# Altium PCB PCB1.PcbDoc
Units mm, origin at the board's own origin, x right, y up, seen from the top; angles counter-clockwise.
Board outline 108.58 x 46.35 mm, 3 copper layers (Top Layer, Mid-Layer 1, Bottom Layer); 29 components, 33 nets, 133 pads, 11 vias.
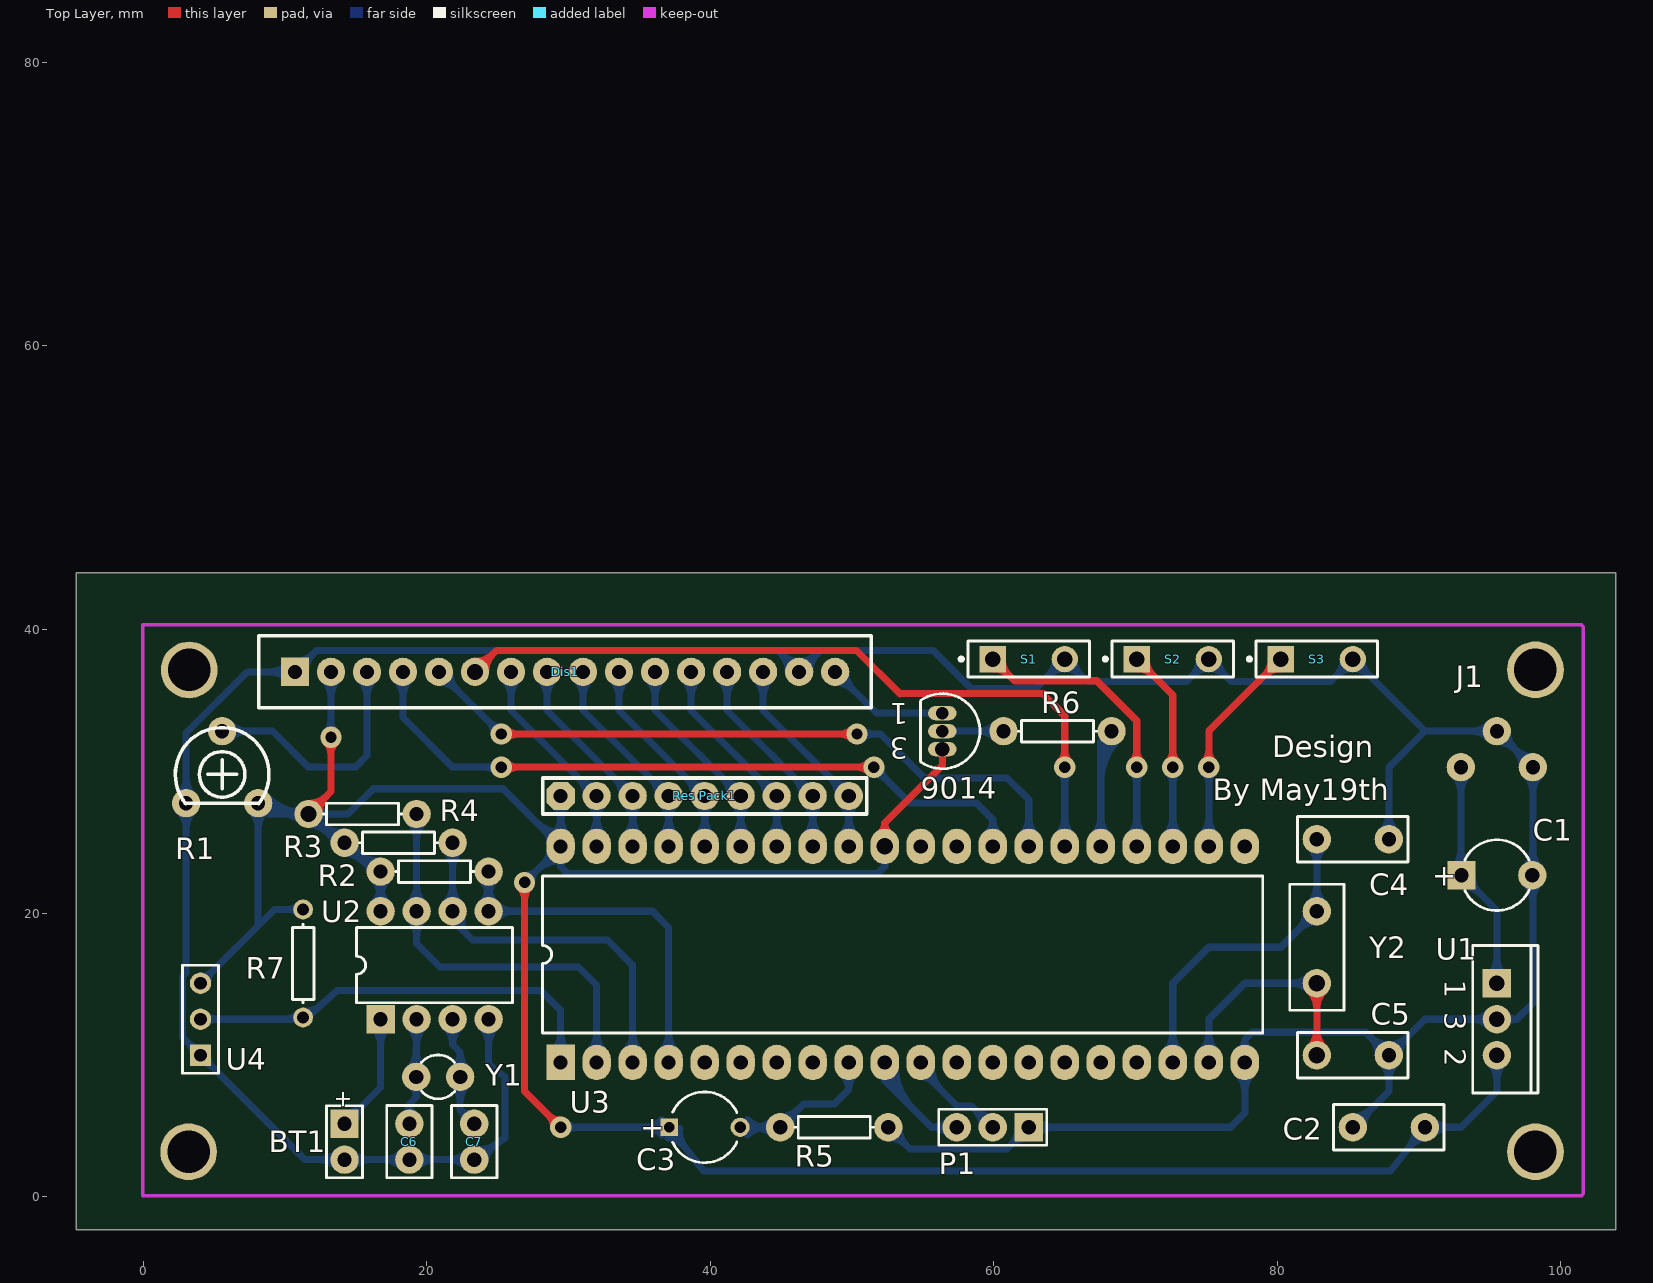
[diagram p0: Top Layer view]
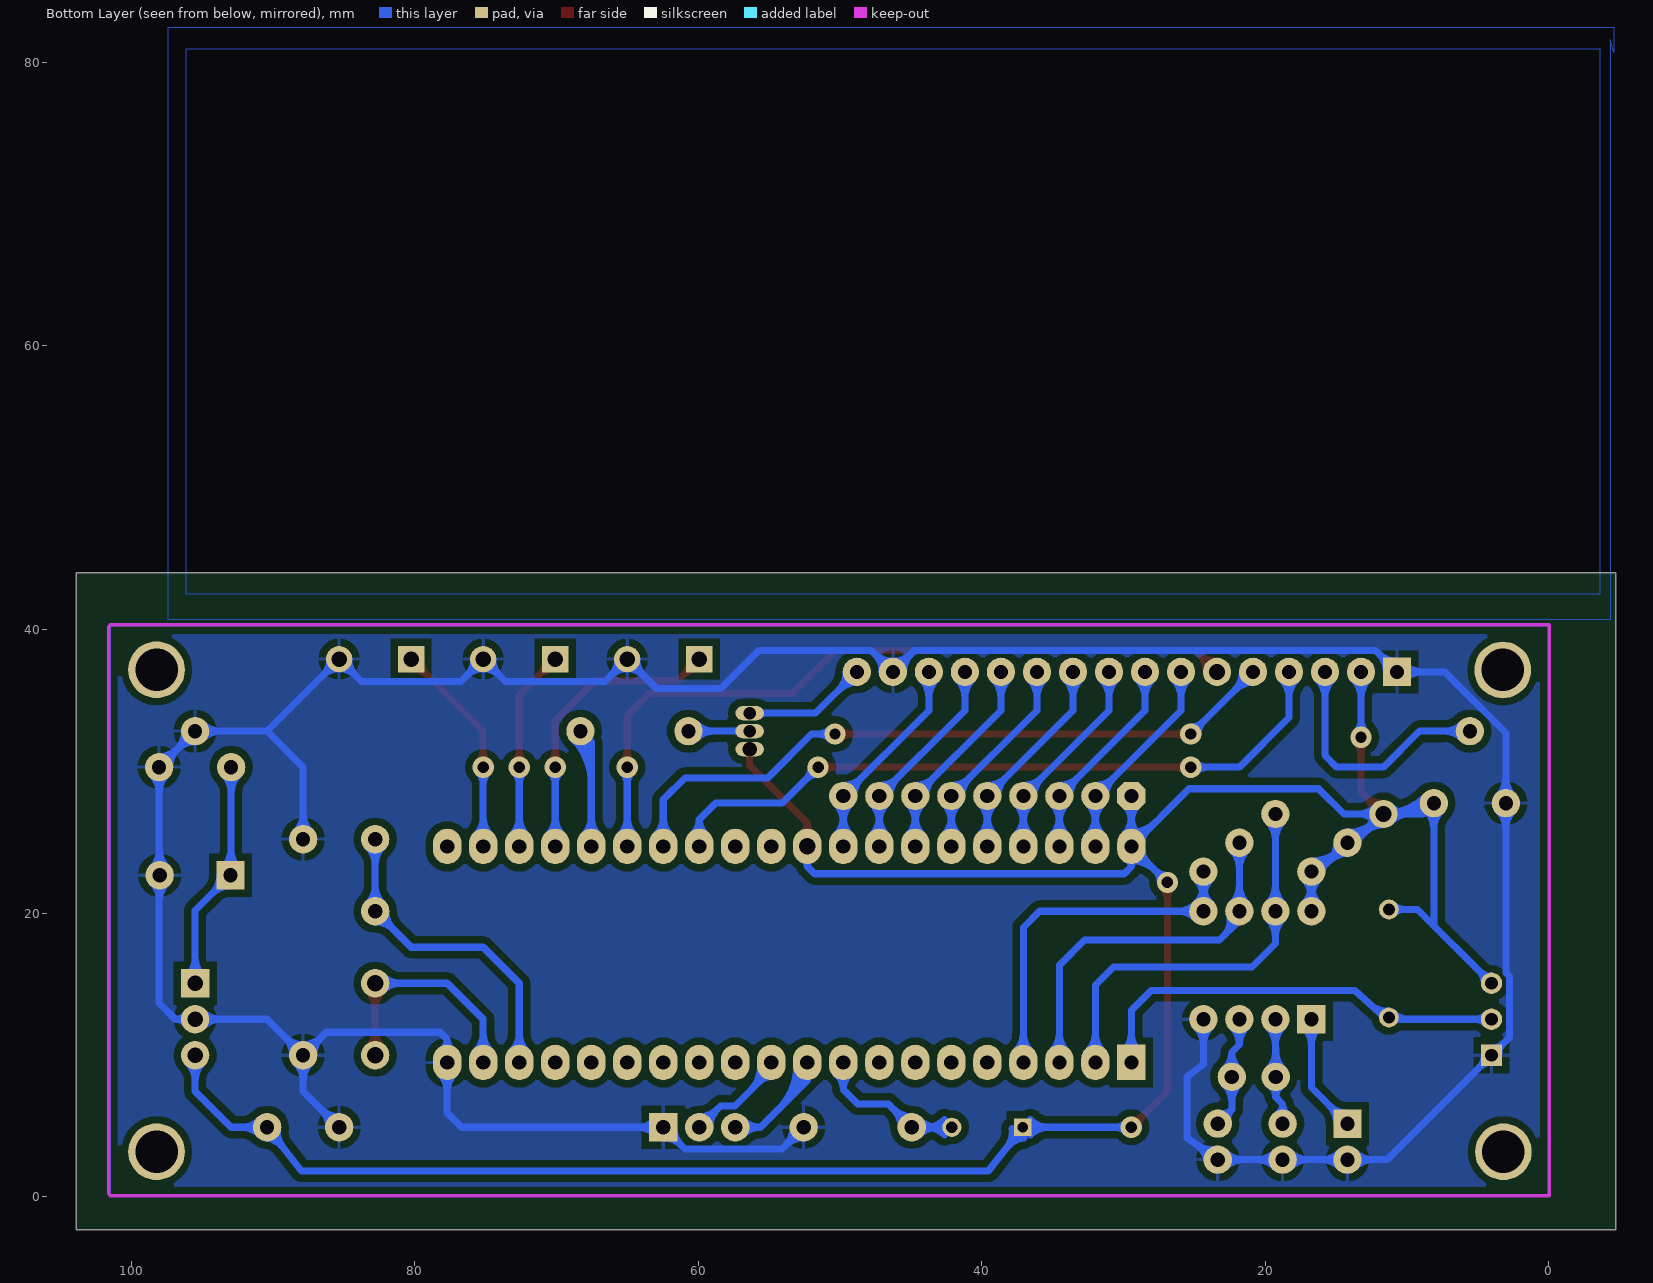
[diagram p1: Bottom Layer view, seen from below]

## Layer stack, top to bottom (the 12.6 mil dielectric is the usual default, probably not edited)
Top Layer: signal copper 0.0356
Dielectric: dielectric 0.32, FR-4, Dk 4.8
Mid-Layer 1: signal copper 0.0356
Dielectric: dielectric 0.32, FR-4, Dk 4.8
Bottom Layer: signal copper 0.0356

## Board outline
-4.715,43.623 -4.715,-2.351 103.87,-2.351 103.87,44.004 -4.715,44.004

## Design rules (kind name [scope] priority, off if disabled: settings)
Clearance [All] p1: gap=0.254
ComponentClearance [All] p1: gap=0.254 collisioncheckmode=0
PolygonConnect [All] p1: connectstyle=Relief reliefconductorwidth=0.254 reliefentries=4 polygonreliefangle="90 Angle"
RoutingVias [All] p1: holewidth=0.711 width=1.27 viastyle="Through Hole" minholewidth=0.711 minwidth=1.27 maxholewidth=0.711 maxwidth=1.27
SolderMaskExpansion [All] p1: expansion=0.203
TestPointUsage [All] p1: valid=0 allowmultiple=FALSE
Testpoint [All] p1: side=15 testpointundercomponent=TRUE minsize=1.016 maxsize=2.54 preferedsize=1.524 minholesize=0 maxholesize=1.016 preferedholesize=0.813 testpointgrid=0.025 style=1023 order=-539222988
Width [All] p1: maxlimit=0.5 minlimit=0.254 preferedwidth=0.254 toplayer_minwidth=0.5 toplayer_prefwidth=0.5 midlayer1_maxwidth=0.254 bottomlayer_minwidth=0.5 bottomlayer_prefwidth=0.5 minimp=50.000000 maximp=50.000000 favimp=50.000000
17 further rules are at their usual default settings.

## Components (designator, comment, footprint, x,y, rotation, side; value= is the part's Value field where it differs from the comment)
9014 "NPN" BCY-W3 56.372,32.828 r180 top (schematic designator Q1)
BT1 "Battery" BAT-2 14.208,3.872 r270 top
C1 "Cap Pol1" CAPPR5-5x5#1 95.488,22.668 r0 top
C2 "Cap" CAPR5.08-7.8x3.2#1 87.868,4.888 r0 top
C3 "Cap Pol1" CAPPR5-5x5#2 39.608,4.888 r0 top
C4 "Cap" CAPR5.08-7.8x3.2#1 85.328,25.208 r180 top
C5 "Cap" CAPR5.08-7.8x3.2#2 85.328,9.968 r180 top
C6 "Cap" CAPR2.54-5.1x3.2 18.78,3.872 r90 top
C7 "Cap" CAPR2.54-5.1x3.2 23.352,3.872 r90 top
Dis1 "LCD1602 BIG" 1602 10.708,37.008 r0 top locked
J1 "电源插头" "电源插头 小" 92.948,30.288 r90 top
P1 "Header 3" HDR1X3#1 62.468,4.888 r180 top
R1 "RPot" 蓝白可调 5.572,32.828 r0 top
R2 "Res1" AXIAL-0.3#1 20.558,22.922 r180 top
R3 "Res1" AXIAL-0.3#1 18.018,24.954 r180 top
R4 "Res1" AXIAL-0.3#2 15.478,26.986 r180 top
R5 "Res1" AXIAL-0.3#1 48.752,4.888 r180 top
R6 "Res1" AXIAL-0.3#1 64.5,32.828 r180 top
R7 "Res1" AXIAL-0.3#3 11.287,16.445 r270 top
"Res Pack1" "RES Pack" "Res Pack" 29.448,28.256 r90 top locked
S1 "SW-PB" SPST-2 62.468,37.908 r0 top
S2 "SW-PB" SPST-2 72.628,37.908 r0 top
S3 "SW-PB" SPST-2 82.788,37.908 r0 top
U1 "L7805AB-V" TO220ABN 95.488,12.508 r270 top
U2 "DS1302" DIP8 20.558,16.318 r0 top
U3 "STC89C51" DIP40 29.448,9.46 r90 top
U4 "DS18b20" HDR1X3#2 4.048,9.968 r90 top
Y1 "XTAL" BCY-W2/D3.1 20.812,8.444 r270 top
Y2 "XTAL" RAD-0.2 82.788,17.588 r270 top

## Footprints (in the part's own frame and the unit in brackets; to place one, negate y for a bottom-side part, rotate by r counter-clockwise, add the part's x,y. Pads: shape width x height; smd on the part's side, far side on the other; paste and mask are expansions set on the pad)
1602 [mm]
  rect 2x2 hole 1: 1(0,0)
  round 2 hole 1: 2(2.54,0) 3(5.08,0) 4(7.62,0) 5(10.16,0) 7(15.24,0) 8(17.78,0) 9(20.32,0) 10(22.86,0) 11(25.4,0) 12(27.94,0) 13(30.48,0) 14(33.02,0) 15(35.56,0) 16(38.1,0)
  round 2 hole 1.15: 6(12.7,0)
  silkscreen extent -2.54,-2.54 40.64,2.54
AXIAL-0.3#1 [mm] "Resistor; 2 Leads"
  round 2 hole 1: 1(-3.81,0) 2(3.81,0)
  silkscreen extent -2.77,-0.76 2.77,0.76
AXIAL-0.3#2 [mm] "Resistor; 2 Leads"
  round 2 hole 1: 1(-3.81,0)
  round 2 hole 1.15: 2(3.81,0)
  silkscreen extent -2.77,-0.76 2.77,0.76
AXIAL-0.3#3 [mm] "Resistor; 2 Leads"
  round 1.4 hole 0.85: 1(-3.81,0) 2(3.81,0)
  silkscreen extent -2.77,-0.76 2.77,0.76
BAT-2 [mm] "Multicell Battery; 2 Leads"
  rect 2x2 hole 1: 1(-1.27,0)
  round 2 hole 1: 2(1.27,0)
  silkscreen extent -2.54,-1.27 2.54,1.27
BCY-W2/D3.1 [mm] "Crystal, Thru-Hole; 2 Leads; Body 3.1 x 8.2 mm (Dia.xH)"
  round 2 hole 1: 1(0,1.55) 2(0,-1.55)
  silkscreen extent -1.55,-1.19 1.55,1.17
BCY-W3 [mm] "TO, Flat Index; 3 In-Line, Axial Leads; Body Dia. 4.8mm"
  oval 2x1 hole 0.9: 1(0,-1.27) 2(0,0)
  oval 2x1 hole 1: 3(0,1.27)
  silkscreen extent -2.65,-2.65 1.55,2.65
CAPPR5-5x5#1 [mm] "Capacitor, Electrolytic, Radial; Body 5 x 5 mm (Dia.xH typ); Pin Spacing 5 mm (typ)"
  rect 2x2 hole 1: 1(-2.5,0)
  round 2 hole 1: 2(2.5,0)
  silkscreen extent -2.26,-2.5 2.27,2.5
CAPPR5-5x5#2 [mm] "Capacitor, Electrolytic, Radial; Body 5 x 5 mm (Dia.xH typ); Pin Spacing 5 mm (typ)"
  rect 1.25x1.25 hole 0.75: 1(-2.5,0)
  round 1.35 hole 0.8: 2(2.5,0)
  silkscreen extent -2.26,-2.5 2.27,2.5
CAPR2.54-5.1x3.2 [mm] "Capacitor, Ceramic, Thru-Hole, Dipped Radial; Body 5.1 x 3.2 mm (WxT) Pin Spacing 2.54 mm (typ)"
  round 2 hole 1: 1(-1.27,0) 2(1.27,0)
  silkscreen extent -2.55,-1.6 2.55,1.6
CAPR5.08-7.8x3.2#1 [mm] "Capacitor, Ceramic, Thru-Hole, Dipped Radial; Body 7.8 x 3.2 mm (WxT) Pin Spacing 5.08 mm (typ)"
  round 2 hole 1: 1(-2.54,0) 2(2.54,0)
  silkscreen extent -3.9,-1.6 3.9,1.6
CAPR5.08-7.8x3.2#2 [mm] "Capacitor, Ceramic, Thru-Hole, Dipped Radial; Body 7.8 x 3.2 mm (WxT) Pin Spacing 5.08 mm (typ)"
  round 2 hole 1: 1(-2.54,0)
  round 2 hole 1.15: 2(2.54,0)
  silkscreen extent -3.9,-1.6 3.9,1.6
DIP8 [mm] "DIP; 8 Leads; Row Spacing 7.62 mm; Pitch 2.54 mm"
  rect 2x2 hole 1: 1(-3.81,-3.81)
  round 2 hole 1: 2(-1.27,-3.81) 3(1.27,-3.81) 4(3.81,-3.81) 5(3.81,3.81) 6(1.27,3.81) 7(-1.27,3.81) 8(-3.81,3.81)
  silkscreen extent -5.5,-2.65 5.5,2.65
DIP40 [mm]
  rect 2.5x2 hole 1: 1(0,0)
  oval 2.5x2 hole 1: 2(0,-2.54) 3(0,-5.08) 4(0,-7.62) 5(0,-10.16) 6(0,-12.7) 7(0,-15.24) 8(0,-17.78) 9(0,-20.32) 10(0,-22.86) 11(0,-25.4) 12(0,-27.94) 13(0,-30.48) 14(0,-33.02) 15(0,-35.56) 16(0,-38.1) 17(0,-40.64) 18(0,-43.18) 19(0,-45.72) 20(0,-48.26) 21(15.24,-48.26) 22(15.24,-45.72) 23(15.24,-43.18) 24(15.24,-40.64) 25(15.24,-38.1) 26(15.24,-35.56) 27(15.24,-33.02) 28(15.24,-30.48) 29(15.24,-27.94) 30(15.24,-25.4) 32(15.24,-20.32) 33(15.24,-17.78) 34(15.24,-15.24) 35(15.24,-12.7) 36(15.24,-10.16) 37(15.24,-7.62) 38(15.24,-5.08) 39(15.24,-2.54) 40(15.24,0)
  oval 2.5x2 hole 1.15: 31(15.24,-22.86)
  silkscreen extent 2.08,-49.53 13.16,1.27
HDR1X3#1 [mm] "Connector; Header; 3 Position"
  rect 2x2 hole 1: 1(0,0)
  round 2 hole 1: 2(2.54,0) 3(5.08,0)
  silkscreen extent -1.27,-1.27 6.35,1.27
HDR1X3#2 [mm] "Connector; Header; 3 Position"
  rect 1.5x1.5 hole 0.9: 1(0,0)
  round 1.5 hole 0.9: 2(2.54,0) 3(5.08,0)
  silkscreen extent -1.27,-1.27 6.35,1.27
RAD-0.2 [mm] "Jumper Wire; 2 Leads"
  round 2 hole 1: 1(-2.54,0)
  round 2 hole 1.15: 2(2.54,0)
  silkscreen extent -4.44,-1.91 4.44,1.91
"Res Pack" [mm]
  oct 2x2 hole 1: 1(0,0)
  round 2 hole 1: 2(0,-2.54) 3(0,-5.08) 4(0,-7.62) 5(0,-10.16) 6(0,-12.7) 7(0,-15.24) 8(0,-17.78) 9(0,-20.32)
  silkscreen extent -1.27,-21.59 1.27,1.27
SPST-2 [mm] "Circuit Breaker; 2 Leads"
  rect 1.85x1.85 hole 1.1: 1(-2.54,0)
  round 1.85 hole 1.1: 2(2.54,0)
  silkscreen extent -4.89,-1.27 4.28,1.27
TO220ABN [mm] "TO, Thru-Hole, Vertical, Heatsink Mounted; 3 In-Line Leads; Pitch 2.54 mm; Pin sequence 1, 3, 2"
  rect 2x2 hole 1.1: 1(-2.54,0)
  round 2 hole 1.1: 2(2.54,0) 3(0,0)
  silkscreen extent -5.2,-1.7 5.2,2.9
"电源插头 小" [mm]
  round 2 hole 1: 1(0,0) 2(0,-5.08) 3(2.54,-2.54)
蓝白可调 [mm]
  round 2 hole 1: 1(0,0) 2(-2.54,-5.08) 3(2.54,-5.08)
  silkscreen extent -3.3,-5.11 3.3,0.25

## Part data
9014: "NPN Bipolar Transistor"
BT1: "Multicell Battery"
C1 C3: "Polarized Capacitor (Radial)"
C2 C4 C5 C6 C7: "Capacitor"
P1: "Header, 3-Pin"
R1: "Potentiometer"
R2 R3 R4 R5 R6 R7: "Resistor"
S1 S2 S3: "Switch"
U1: "Precision 1A Regulator"
Y1 Y2: "Crystal Oscillator"

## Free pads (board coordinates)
  round 4 hole 3: 0(3.25,37.146) 1(3.208,3.159) 1(98.208,37.159) 2(98.208,3.159)

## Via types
v1: diameter 1.5, hole 0.8, Top Layer to Bottom Layer, 11 vias

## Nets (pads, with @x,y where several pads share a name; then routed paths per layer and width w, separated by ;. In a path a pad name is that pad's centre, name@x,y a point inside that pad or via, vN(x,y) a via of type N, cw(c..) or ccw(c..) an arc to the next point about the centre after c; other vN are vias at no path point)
GND: BT1.2 C1.2 C2.1 C4.1 C5.1 C6.1 C7.1 Dis1.1 Dis1.15 J1.2 J1.3 P1.1 R1.2 R5.1 S1.2 S2.2 S3.2 U1.3 U2.4 U3.20 U4.1 | length 460.3
  Bottom Layer w0.5: U2.4 24.368,9.333 25.511,8.444 25.511,4.126 C7.1 C6.1 BT1.2 11.414,2.602 U4.1 2.778,11.238 2.778,15.531 3.032,15.785 3.032,32.701 7.339,37.008 Dis1.1 12.217,38.518 44.758,38.518 Dis1.15 47.777,38.518 55.737,38.518 58.429,35.825 62.925,35.825 S1.2 66.583,36.333 73.593,36.333 S2.2 76.743,36.333 83.753,36.333 S3.2 90.408,32.828 ; R5.1 54.086,3.364 60.944,3.364 P1.1 76.692,4.888 77.708,5.904 U3.20 77.708,11.086 ; C2.1 87.868,7.428 C5.1 ; C4.1 87.868,30.288 90.408,32.828 ; 3.032,25.937 cw(c4.843,25.937) 3.562,27.218 ccw(c4.843,25.937) 3.032,25.937 ; 3.032,25.937 ccw(c1.221,25.937) 2.502,27.218 cw(c1.221,25.937) 3.032,25.937 ; 3.032,29.559 cw(c1.221,29.559) 2.502,28.278 ccw(c1.221,29.559) 3.032,29.559 ; 3.032,29.559 ccw(c4.843,29.559) 3.562,28.278 cw(c4.843,29.559) 3.032,29.559 ; 3.194,10.822 cw(c2.341,9.968) 3.548,9.968 ccw(c2.341,9.968) 3.194,10.822 ; 3.194,10.822 ccw(c4.048,11.675) 4.048,10.468 cw(c4.048,11.675) 3.194,10.822 ; 4.901,9.115 cw(c5.755,9.968) 4.548,9.968 ccw(c5.755,9.968) 4.901,9.115 ; 4.901,9.115 ccw(c4.048,8.261) 4.048,9.468 cw(c4.048,8.261) 4.901,9.115 ; 8.897,37.008 cw(c8.897,35.197) 10.178,36.478 ccw(c8.897,35.197) 8.897,37.008 ; 8.897,37.008 ccw(c8.897,38.819) 10.178,37.538 cw(c8.897,38.819) 8.897,37.008 ; 11.988,38.288 cw(c10.708,39.569) 10.708,37.758 ccw(c10.708,39.569) 11.988,38.288 ; 11.988,38.288 ccw(c13.269,37.008) 11.458,37.008 cw(c13.269,37.008) 11.988,38.288 ; 12.397,2.602 cw(c12.397,0.791) 13.678,2.072 ccw(c12.397,0.791) 12.397,2.602 ; 12.397,2.602 ccw(c12.397,4.413) 13.678,3.132 cw(c12.397,4.413) 12.397,2.602 ; 16.019,2.602 cw(c16.019,4.413) 14.738,3.132 ccw(c16.019,4.413) 16.019,2.602 ; 16.019,2.602 ccw(c16.019,0.791) 14.738,2.072 cw(c16.019,0.791) 16.019,2.602 ; 16.969,2.602 cw(c16.969,0.791) 18.25,2.072 ccw(c16.969,0.791) 16.969,2.602 ; 16.969,2.602 ccw(c16.969,4.413) 18.25,3.132 cw(c16.969,4.413) 16.969,2.602 ; 20.591,2.602 cw(c20.591,4.413) 19.31,3.132 ccw(c20.591,4.413) 20.591,2.602 ; 20.591,2.602 ccw(c20.591,0.791) 19.31,2.072 cw(c20.591,0.791) 20.591,2.602 ; 21.541,2.602 cw(c21.541,0.791) 22.822,2.072 ccw(c21.541,0.791) 21.541,2.602 ; 21.541,2.602 ccw(c21.541,4.413) 22.822,3.132 cw(c21.541,4.413) 21.541,2.602 ; 24.368,10.697 cw(c26.179,10.697) 24.898,11.978 ccw(c26.179,10.697) 24.368,10.697 ; 24.368,10.697 ccw(c22.557,10.697) 23.838,11.978 cw(c22.557,10.697) 24.368,10.697 ; 24.831,3.646 cw(c23.787,5.126) 23.479,3.341 ccw(c23.787,5.126) 24.831,3.646 ; 24.831,3.646 ccw(c25.875,2.167) 24.091,2.475 cw(c25.875,2.167) 24.831,3.646 ; 44.988,38.288 cw(c43.707,37.008) 45.518,37.008 ccw(c43.707,37.008) 44.988,38.288 ; 44.988,38.288 ccw(c46.268,39.569) Dis1.15@46.268,37.758 ; 44.988,38.288 ccw(c46.268,39.569) Dis1.15@46.268,37.758 ; Dis1.15@46.268,37.758 ccw(c46.268,39.569) 47.548,38.288 ; Dis1.15@46.268,37.758 ccw(c46.268,39.569) 47.548,38.288 ; 47.548,38.288 ccw(c48.829,37.008) 47.018,37.008 cw(c48.829,37.008) 47.548,38.288 ; 53.842,3.608 cw(c55.123,4.888) 53.312,4.888 ccw(c55.123,4.888) 53.842,3.608 ; 53.842,3.608 ccw(c52.562,2.327) 52.562,4.138 cw(c52.562,2.327) 53.842,3.608 ; 61.188,3.608 cw(c62.468,2.327) 62.468,4.138 ccw(c62.468,2.327) 61.188,3.608 ; 61.188,3.608 ccw(c59.907,4.888) 61.718,4.888 cw(c59.907,4.888) 61.188,3.608 ; 63.856,36.756 cw(c65.008,35.604) S1.2@65.008,37.233 ; 63.856,36.756 ccw(c62.703,37.908) 64.333,37.908 cw(c62.703,37.908) 63.856,36.756 ; 63.856,36.756 cw(c65.008,35.604) S1.2@65.008,37.233 ; 64.279,4.888 cw(c64.279,6.699) 62.998,5.418 ccw(c64.279,6.699) 64.279,4.888 ; 64.279,4.888 ccw(c64.279,3.077) 62.998,4.358 cw(c64.279,3.077) 64.279,4.888 ; S1.2@65.008,37.233 cw(c65.008,35.604) 66.16,36.756 ; S1.2@65.008,37.233 cw(c65.008,35.604) 66.16,36.756 ; 66.16,36.756 cw(c67.312,37.908) 65.683,37.908 ccw(c67.312,37.908) 66.16,36.756 ; 74.016,36.756 cw(c75.168,35.604) S2.2@75.168,37.233 ; 74.016,36.756 ccw(c72.863,37.908) 74.493,37.908 cw(c72.863,37.908) 74.016,36.756 ; 74.016,36.756 cw(c75.168,35.604) S2.2@75.168,37.233 ; S2.2@75.168,37.233 cw(c75.168,35.604) 76.32,36.756 ; S2.2@75.168,37.233 cw(c75.168,35.604) 76.32,36.756 ; 76.32,36.756 cw(c77.472,37.908) 75.843,37.908 ccw(c77.472,37.908) 76.32,36.756 ; 77.708,7.399 cw(c79.519,7.399) 78.238,8.68 ccw(c79.519,7.399) 77.708,7.399 ; 77.708,7.399 ccw(c75.897,7.399) 77.178,8.68 cw(c75.897,7.399) 77.708,7.399 ; 77.708,11.086 cw(c76.821,11.086) 77.302,10.341 ccw(c76.821,11.086) 77.708,11.086 ; 77.708,11.086 ccw(c78.594,11.086) 78.114,10.341 cw(c78.594,11.086) 77.708,11.086 ; 77.708,11.086 78.216,11.594 86.242,11.594 C5.1 ; 84.176,36.756 cw(c85.328,35.604) S3.2@85.328,37.233 ; 84.176,36.756 ccw(c83.023,37.908) 84.653,37.908 cw(c83.023,37.908) 84.176,36.756 ; 84.176,36.756 cw(c85.328,35.604) S3.2@85.328,37.233 ; S3.2@85.328,37.233 cw(c85.328,35.604) 86.48,36.756 ; S3.2@85.328,37.233 cw(c85.328,35.604) 86.48,36.756 ; 86.48,36.756 cw(c87.632,37.908) 86.003,37.908 ccw(c87.632,37.908) 86.48,36.756 ; 86.588,11.248 cw(c85.307,9.968) 87.118,9.968 ccw(c85.307,9.968) 86.588,11.248 ; 86.588,11.248 ccw(c87.868,12.529) C5.1@87.868,10.718 ; 86.588,11.248 ccw(c87.868,12.529) C5.1@87.868,10.718 ; 86.608,6.168 cw(c85.328,7.449) 85.328,5.638 ccw(c85.328,7.449) 86.608,6.168 ; 86.608,6.168 ccw(c87.889,4.888) 86.078,4.888 cw(c87.889,4.888) 86.608,6.168 ; 87.868,8.157 cw(c89.679,8.157) 88.398,9.438 ccw(c89.679,8.157) 87.868,8.157 ; 87.868,8.157 ccw(c86.057,8.157) 87.338,9.438 cw(c86.057,8.157) 87.868,8.157 ; C5.1 90.408,12.508 U1.3 96.885,12.508 ; C5.1@87.868,10.718 ccw(c87.868,12.529) 89.148,11.248 ; C5.1@87.868,10.718 ccw(c87.868,12.529) 89.148,11.248 ; 87.868,27.019 cw(c86.057,27.019) 87.338,25.738 ccw(c86.057,27.019) 87.868,27.019 ; 87.868,27.019 ccw(c89.679,27.019) 88.398,25.738 cw(c89.679,27.019) 87.868,27.019 ; 89.148,11.248 ccw(c90.429,9.968) 88.618,9.968 cw(c90.429,9.968) 89.148,11.248 ; 90.408,32.828 J1.3 J1.2 98.028,22.668 98.028,13.651 96.885,12.508 ; 93.677,12.508 cw(c93.677,10.697) 94.958,11.978 ccw(c93.677,10.697) 93.677,12.508 ; 93.677,12.508 ccw(c93.677,14.319) 94.958,13.038 cw(c93.677,14.319) 93.677,12.508 ; 93.677,32.828 cw(c93.677,31.017) 94.958,32.298 ccw(c93.677,31.017) 93.677,32.828 ; 93.677,32.828 ccw(c93.677,34.639) 94.958,33.358 cw(c93.677,34.639) 93.677,32.828 ; 96.748,31.568 cw(c95.467,30.288) 97.278,30.288 ccw(c95.467,30.288) 96.748,31.568 ; 96.748,31.568 ccw(c98.028,32.849) 98.028,31.038 cw(c98.028,32.849) 96.748,31.568 ; 96.768,31.548 cw(c98.049,32.828) 96.238,32.828 ccw(c98.049,32.828) 96.768,31.548 ; 96.768,31.548 ccw(c95.488,30.267) 95.488,32.078 cw(c95.488,30.267) 96.768,31.548 ; 96.885,12.508 cw(c96.885,13.434) 96.113,12.922 ccw(c96.885,13.434) 96.885,12.508 ; 96.885,12.508 ccw(c96.885,11.582) 96.113,12.094 cw(c96.885,11.582) 96.885,12.508 ; 98.028,28.477 cw(c99.839,28.477) 98.558,29.758 ccw(c99.839,28.477) 98.028,28.477 ; 98.028,28.477 ccw(c96.217,28.477) 97.498,29.758 cw(c96.217,28.477) 98.028,28.477 ; C1.2@97.458,22.138 cw(c96.081,20.761) 98.028,20.761 ccw(c96.081,20.761) C1.2@97.458,22.138 ; C1.2@97.458,23.198 ccw(c96.081,24.575) 98.028,24.575 cw(c96.081,24.575) C1.2@97.458,23.198 ; 98.028,20.954 cw(c99.702,20.954) 98.518,22.138 ccw(c99.702,20.954) 98.028,20.954 ; 98.028,24.382 ccw(c99.702,24.382) 98.518,23.198 cw(c99.702,24.382) 98.028,24.382
LEDA: R6.1 U3.25 | length 31.2
  Bottom Layer w0.5: U3.25 67.548,32.066 ; R6.1 67.548,32.066 ; 67.548,26.761 cw(c65.737,26.761) 67.018,25.48 ccw(c65.737,26.761) 67.548,26.761 ; 67.548,26.761 ccw(c69.359,26.761) 68.078,25.48 cw(c69.359,26.761) 67.548,26.761 ; 67.548,32.066 cw(c67.83,31.784) 67.997,32.147 ccw(c67.83,31.784) 67.548,32.066 ; 67.548,32.066 ccw(c67.266,32.348) 67.628,32.515 cw(c67.266,32.348) 67.548,32.066 ; 67.548,29.178 cw(c71.96,29.178) 68.84,32.298 ccw(c71.96,29.178) 67.548,29.178 ; 67.548,30.385 cw(c70.753,30.385) 68.487,32.651 ccw(c70.753,30.385) 67.548,30.385 ; 67.548,31.592 cw(c69.546,31.592) 68.133,33.005 ccw(c69.546,31.592) 67.548,31.592
NetBT1_1: BT1.1 U2.1 | length 19.8
  Bottom Layer w0.5: BT1.1 16.748,7.682 U2.1 ; 15.488,6.422 cw(c14.208,7.703) 14.208,5.892 ccw(c14.208,7.703) 15.488,6.422 ; 15.488,6.422 ccw(c16.769,5.142) 14.958,5.142 cw(c16.769,5.142) 15.488,6.422 ; 16.748,10.697 cw(c18.559,10.697) 17.278,11.978 ccw(c18.559,10.697) 16.748,10.697 ; 16.748,10.697 ccw(c14.937,10.697) 16.218,11.978 cw(c14.937,10.697) 16.748,10.697
NetC1_1: C1.1 J1.1 U1.1 | length 39
  Bottom Layer w0.5: J1.1 92.948,22.708 C1.1 95.488,20.168 U1.1 ; 92.948,28.477 cw(c94.759,28.477) 93.478,29.758 ccw(c94.759,28.477) 92.948,28.477 ; 92.948,28.477 ccw(c91.137,28.477) 92.418,29.758 cw(c91.137,28.477) 92.948,28.477 ; 94.268,21.388 cw(c95.549,22.668) 93.738,22.668 ccw(c95.549,22.668) 94.268,21.388 ; 94.268,21.388 ccw(c92.988,20.107) 92.988,21.918 cw(c92.988,20.107) 94.268,21.388 ; 95.488,16.859 cw(c93.677,16.859) 94.958,15.578 ccw(c93.677,16.859) 95.488,16.859 ; 95.488,16.859 ccw(c97.299,16.859) 96.018,15.578 cw(c97.299,16.859) 95.488,16.859 ; C1.1@92.458,23.198 ccw(c91.274,24.382) 92.948,24.382 cw(c91.274,24.382) C1.1@92.458,23.198 ; 92.948,24.575 ccw(c94.895,24.575) 93.518,23.198 cw(c94.895,24.575) 92.948,24.575
NetC3_2: C3.2 R5.2 U3.9 | length 31.4
  Bottom Layer w0.5: C3.2 R5.2 46.593,6.539 48.752,6.539 49.768,7.555 ; C3.2@42.408,4.588 cw(c43.134,3.862) 43.134,4.888 cw(c43.134,5.914) C3.2@42.408,5.189 ; 42.638,4.358 cw(c43.919,3.077) 43.919,4.888 cw(c43.919,6.699) 42.638,5.418 ; U3.9 49.768,7.555 ; 43.131,4.888 cw(c43.131,3.077) 44.412,4.358 ccw(c43.131,3.077) 43.131,4.888 ; 43.131,4.888 ccw(c43.131,6.699) 44.412,5.418 cw(c43.131,6.699) 43.131,4.888 ; 46.222,6.168 cw(c44.942,7.449) 44.942,5.638 ccw(c44.942,7.449) 46.222,6.168 ; 46.222,6.168 ccw(c47.503,4.888) 45.692,4.888 cw(c47.503,4.888) 46.222,6.168 ; 49.768,7.555 cw(c51.219,7.555) 50.262,8.646 ccw(c51.219,7.555) 49.768,7.555 ; 49.768,7.555 ccw(c48.317,7.555) 49.273,8.646 cw(c48.317,7.555) 49.768,7.555
NetC4_2: C4.2 U3.18 Y2.1 | length 45.7
  Bottom Layer w0.5: U3.18 72.628,15.048 75.168,17.588 80.248,17.588 Y2.1 C4.2 ; 72.628,11.521 cw(c70.817,11.521) 72.098,10.24 ccw(c70.817,11.521) 72.628,11.521 ; 72.628,11.521 ccw(c74.439,11.521) 73.158,10.24 cw(c74.439,11.521) 72.628,11.521 ; 81.508,18.848 cw(c82.788,17.567) 82.788,19.378 ccw(c82.788,17.567) 81.508,18.848 ; 81.508,18.848 ccw(c80.227,20.128) 82.038,20.128 cw(c80.227,20.128) 81.508,18.848 ; 82.788,21.939 cw(c80.977,21.939) 82.258,20.658 ccw(c80.977,21.939) 82.788,21.939 ; 82.788,21.939 ccw(c84.599,21.939) 83.318,20.658 cw(c84.599,21.939) 82.788,21.939 ; 82.788,23.397 cw(c84.599,23.397) 83.318,24.678 ccw(c84.599,23.397) 82.788,23.397 ; 82.788,23.397 ccw(c80.977,23.397) 82.258,24.678 cw(c80.977,23.397) 82.788,23.397
NetC5_2: C5.2 U3.19 Y2.2 | length 39.6
  Top Layer w0.5: C5.2 Y2.2 ; 82.788,11.779 cw(c80.977,11.779) 82.258,10.498 ccw(c80.977,11.779) 82.788,11.779 ; 82.788,11.779 ccw(c84.599,11.779) 83.318,10.498 cw(c84.599,11.779) 82.788,11.779 ; 82.788,13.237 cw(c84.599,13.237) 83.318,14.518 ccw(c84.599,13.237) 82.788,13.237 ; 82.788,13.237 ccw(c80.977,13.237) 82.258,14.518 cw(c80.977,13.237) 82.788,13.237
  Bottom Layer w0.5: U3.19 75.168,12.508 77.708,15.048 Y2.2 ; 75.168,11.521 cw(c73.357,11.521) 74.638,10.24 ccw(c73.357,11.521) 75.168,11.521 ; 75.168,11.521 ccw(c76.979,11.521) 75.698,10.24 cw(c76.979,11.521) 75.168,11.521 ; 80.977,15.048 cw(c80.977,13.237) 82.258,14.518 ccw(c80.977,13.237) 80.977,15.048 ; 80.977,15.048 ccw(c80.977,16.859) 82.258,15.578 cw(c80.977,16.859) 80.977,15.048
NetC6_2: C6.2 U2.2 Y1.2 | length 26.3
  Bottom Layer w0.5: C6.2 18.78,6.539 ; 19.262,10.451 Y1.2 19.262,7.021 ; 19.288,10.477 U2.2 ; 18.78,6.539 cw(c17.854,6.539) 18.366,5.767 ccw(c17.854,6.539) 18.78,6.539 ; 18.78,6.539 ccw(c19.706,6.539) 19.194,5.767 cw(c19.706,6.539) 18.78,6.539 ; 18.78,6.539 19.262,7.021 ; 19.262,7.021 cw(c20.237,7.021) 19.686,7.825 ccw(c20.237,7.021) 19.262,7.021 ; 19.262,7.021 ccw(c18.287,7.021) 18.838,7.825 cw(c18.287,7.021) 19.262,7.021 ; 19.262,10.255 cw(c17.451,10.255) 18.732,8.974 ccw(c17.451,10.255) 19.262,10.255 ; 19.262,10.255 ccw(c21.073,10.255) 19.792,8.974 cw(c21.073,10.255) 19.262,10.255 ; 19.288,10.697 cw(c21.099,10.697) 19.818,11.978 ccw(c21.099,10.697) 19.288,10.697 ; 19.288,10.697 ccw(c17.477,10.697) 18.758,11.978 cw(c17.477,10.697) 19.288,10.697
NetC7_2: C7.2 U2.3 Y1.1 | length 28.3
  Bottom Layer w0.5: U2.3 21.828,10.731 22.362,10.197 ; C7.2 22.362,6.132 Y1.1 22.362,10.197 ; 21.828,10.731 cw(c23.559,10.731) 22.351,11.971 ccw(c23.559,10.731) 21.828,10.731 ; 21.828,10.731 ccw(c20.097,10.731) 21.305,11.971 cw(c20.097,10.731) 21.828,10.731 ; 22.362,6.633 cw(c24.173,6.633) 22.892,7.914 ccw(c24.173,6.633) 22.362,6.633 ; 22.362,6.633 ccw(c20.551,6.633) 21.832,7.914 cw(c20.551,6.633) 22.362,6.633 ; 22.362,10.197 cw(c20.689,10.197) 21.844,8.987 ccw(c20.689,10.197) 22.362,10.197 ; 22.362,10.197 ccw(c24.034,10.197) 22.88,8.987 cw(c24.034,10.197) 22.362,10.197 ; 22.362,6.132 cw(c21.703,5.473) 22.617,5.29 ccw(c21.703,5.473) 22.362,6.132 ; 22.362,6.132 ccw(c23.021,6.791) 23.204,5.877 cw(c23.021,6.791) 22.362,6.132
NetDis1_4: Dis1.4 U3.28 | length 75.4
  Top Layer w0.5: v1(25.257,30.288) v1@51.419,30.288 ; 26.464,30.288 cw(c26.464,31.495) 25.61,30.642 ccw(c26.464,31.495) 26.464,30.288 ; 26.464,30.288 ccw(c26.464,29.081) 25.61,29.935 cw(c26.464,29.081) 26.464,30.288 ; 50.339,30.288 cw(c50.339,29.081) 51.192,29.935 ccw(c50.339,29.081) 50.339,30.288 ; 50.339,30.288 ccw(c50.339,31.495) 51.192,30.642 cw(c50.339,31.495) 50.339,30.288
  Bottom Layer w0.5: Dis1.4 18.328,33.788 21.828,30.288 v1(25.257,30.288) ; v1(51.546,30.288) 54.086,27.748 58.785,27.748 59.928,26.605 ; U3.28 59.928,26.605 ; 18.328,35.197 cw(c20.139,35.197) 18.858,36.478 ccw(c20.139,35.197) 18.328,35.197 ; 18.328,35.197 ccw(c16.517,35.197) 17.798,36.478 cw(c16.517,35.197) 18.328,35.197 ; 24.05,30.288 cw(c24.05,29.081) 24.903,29.935 ccw(c24.05,29.081) 24.05,30.288 ; 24.05,30.288 ccw(c24.05,31.495) 24.903,30.642 cw(c24.05,31.495) 24.05,30.288 ; 52.399,29.435 cw(c53.253,30.288) 52.046,30.288 ccw(c53.253,30.288) 52.399,29.435 ; 52.399,29.435 ccw(c51.546,28.581) 51.546,29.788 cw(c51.546,28.581) 52.399,29.435 ; 59.928,26.605 cw(c58.477,26.605) 59.433,25.514 ccw(c58.477,26.605) 59.928,26.605 ; 59.928,26.605 ccw(c61.379,26.605) 60.422,25.514 cw(c61.379,26.605) 59.928,26.605
NetDis1_5: Dis1.5 U3.27 | length 75.2
  Top Layer w0.5: v1(25.251,32.625) v1(50.352,32.625) ; 26.458,32.625 cw(c26.458,33.832) 25.605,32.978 ccw(c26.458,33.832) 26.458,32.625 ; 26.458,32.625 ccw(c26.458,31.418) 25.605,32.271 cw(c26.458,31.418) 26.458,32.625 ; 49.145,32.625 cw(c49.145,31.418) 49.999,32.271 ccw(c49.145,31.418) 49.145,32.625 ; 49.145,32.625 ccw(c49.145,33.832) 49.999,32.978 cw(c49.145,33.832) 49.145,32.625
  Bottom Layer w0.5: Dis1.5 v1(25.251,32.625) ; v1(50.352,32.625) 52.003,32.625 55.102,29.526 60.944,29.526 62.468,28.002 U3.27 ; 22.148,35.728 cw(c23.429,37.008) 21.618,37.008 ccw(c23.429,37.008) 22.148,35.728 ; 22.148,35.728 ccw(c20.868,34.447) 20.868,36.258 cw(c20.868,34.447) 22.148,35.728 ; 24.398,33.478 cw(c23.544,32.625) 24.751,32.625 ccw(c23.544,32.625) 24.398,33.478 ; 24.397,33.478 ccw(c25.251,34.332) 25.251,33.125 cw(c25.251,34.332) 24.397,33.478 ; 51.559,32.625 cw(c51.559,33.832) 50.706,32.978 ccw(c51.559,33.832) 51.559,32.625 ; 51.559,32.625 ccw(c51.559,31.418) 50.706,32.271 cw(c51.559,31.418) 51.559,32.625 ; 62.468,26.761 cw(c60.657,26.761) 61.938,25.48 ccw(c60.657,26.761) 62.468,26.761 ; 62.468,26.761 ccw(c64.279,26.761) 62.998,25.48 cw(c64.279,26.761) 62.468,26.761
NetDis1_6: Dis1.6 U3.26 | length 72.3
  Top Layer w0.5: Dis1.6 24.917,38.518 50.327,38.518 53.4,35.444 ; 24.688,38.288 ccw(c25.969,37.008) 24.158,37.008 cw(c25.969,37.008) 24.688,38.288 ; 53.451,35.495 63.535,35.495 ; 63.484,35.444 65.008,33.92 v1(65.008,30.288) ; 65.008,31.495 ccw(c66.215,31.495) 65.361,30.642 cw(c66.215,31.495) 65.008,31.495 ; 24.688,38.288 cw(c23.408,39.569) 23.408,37.758 ccw(c23.408,39.569) 24.688,38.288 ; 65.008,31.495 cw(c63.801,31.495) 64.654,30.642 ccw(c63.801,31.495) 65.008,31.495
  Bottom Layer w0.5: U3.26 v1(65.008,30.288) ; 65.008,29.081 cw(c66.215,29.081) 65.361,29.935 ccw(c66.215,29.081) 65.008,29.081 ; 65.008,26.761 cw(c63.197,26.761) 64.478,25.48 ccw(c63.197,26.761) 65.008,26.761 ; 65.008,26.761 ccw(c66.819,26.761) 65.538,25.48 cw(c66.819,26.761) 65.008,26.761 ; 65.008,29.081 ccw(c63.801,29.081) 64.654,29.935 cw(c63.801,29.081) 65.008,29.081
NetDis1_7: "Res Pack1.2" Dis1.7 U3.39 | length 37.6
  Bottom Layer w0.5: Dis1.7 25.948,34.296 31.988,28.256 U3.39 ; 25.948,35.197 cw(c27.758,35.197) 26.478,36.478 ccw(c27.758,35.197) 25.948,35.197 ; 25.948,35.197 ccw(c24.137,35.197) 25.418,36.478 cw(c24.137,35.197) 25.948,35.197 ; 30.708,29.536 cw(c29.427,28.256) 31.238,28.256 ccw(c29.427,28.256) 30.708,29.536 ; 30.708,29.536 ccw(c31.988,30.817) 31.988,29.006 cw(c31.988,30.817) 30.708,29.536 ; 31.988,26.445 cw(c33.799,26.445) 32.518,27.726 ccw(c33.799,26.445) 31.988,26.445 ; 31.988,26.445 ccw(c30.177,26.445) 31.458,27.726 cw(c30.177,26.445) 31.988,26.445 ; 31.988,26.761 cw(c30.177,26.761) 31.458,25.48 ccw(c30.177,26.761) 31.988,26.761 ; 31.988,26.761 ccw(c33.799,26.761) 32.518,25.48 cw(c33.799,26.761) 31.988,26.761
NetDis1_8: "Res Pack1.3" Dis1.8 U3.38 | length 37.6
  Bottom Layer w0.5: Dis1.8 28.488,34.296 34.528,28.256 U3.38 ; 28.488,35.197 cw(c30.298,35.197) 29.018,36.478 ccw(c30.298,35.197) 28.488,35.197 ; 28.488,35.197 ccw(c26.677,35.197) 27.958,36.478 cw(c26.677,35.197) 28.488,35.197 ; 33.248,29.536 cw(c31.967,28.256) 33.778,28.256 ccw(c31.967,28.256) 33.248,29.536 ; 33.248,29.536 ccw(c34.528,30.817) 34.528,29.006 cw(c34.528,30.817) 33.248,29.536 ; 34.528,26.445 cw(c36.339,26.445) 35.058,27.726 ccw(c36.339,26.445) 34.528,26.445 ; 34.528,26.445 ccw(c32.717,26.445) 33.998,27.726 cw(c32.717,26.445) 34.528,26.445 ; 34.528,26.761 cw(c32.717,26.761) 33.998,25.48 ccw(c32.717,26.761) 34.528,26.761 ; 34.528,26.761 ccw(c36.339,26.761) 35.058,25.48 cw(c36.339,26.761) 34.528,26.761
NetDis1_9: "Res Pack1.4" Dis1.9 U3.37 | length 37.6
  Bottom Layer w0.5: Dis1.9 31.028,34.296 37.068,28.256 U3.37 ; 31.028,35.197 cw(c32.838,35.197) 31.558,36.478 ccw(c32.838,35.197) 31.028,35.197 ; 31.028,35.197 ccw(c29.217,35.197) 30.498,36.478 cw(c29.217,35.197) 31.028,35.197 ; 35.788,29.536 cw(c34.507,28.256) 36.318,28.256 ccw(c34.507,28.256) 35.788,29.536 ; 35.788,29.536 ccw(c37.068,30.817) 37.068,29.006 cw(c37.068,30.817) 35.788,29.536 ; 37.068,26.445 cw(c38.879,26.445) 37.598,27.726 ccw(c38.879,26.445) 37.068,26.445 ; 37.068,26.445 ccw(c35.257,26.445) 36.538,27.726 cw(c35.257,26.445) 37.068,26.445 ; 37.068,26.761 cw(c35.257,26.761) 36.538,25.48 ccw(c35.257,26.761) 37.068,26.761 ; 37.068,26.761 ccw(c38.879,26.761) 37.598,25.48 cw(c38.879,26.761) 37.068,26.761
NetDis1_10: "Res Pack1.5" Dis1.10 U3.36 | length 37.6
  Bottom Layer w0.5: Dis1.10 33.568,34.296 39.608,28.256 U3.36 ; 33.568,35.197 cw(c35.378,35.197) 34.098,36.478 ccw(c35.378,35.197) 33.568,35.197 ; 33.568,35.197 ccw(c31.757,35.197) 33.038,36.478 cw(c31.757,35.197) 33.568,35.197 ; 38.328,29.536 cw(c37.047,28.256) 38.858,28.256 ccw(c37.047,28.256) 38.328,29.536 ; 38.328,29.536 ccw(c39.608,30.817) 39.608,29.006 cw(c39.608,30.817) 38.328,29.536 ; 39.608,26.445 cw(c41.419,26.445) 40.138,27.726 ccw(c41.419,26.445) 39.608,26.445 ; 39.608,26.445 ccw(c37.797,26.445) 39.078,27.726 cw(c37.797,26.445) 39.608,26.445 ; 39.608,26.761 cw(c37.797,26.761) 39.078,25.48 ccw(c37.797,26.761) 39.608,26.761 ; 39.608,26.761 ccw(c41.419,26.761) 40.138,25.48 cw(c41.419,26.761) 39.608,26.761
NetDis1_11: "Res Pack1.6" Dis1.11 U3.35 | length 37.6
  Bottom Layer w0.5: Dis1.11 36.108,34.296 42.148,28.256 U3.35 ; 36.108,35.197 cw(c37.918,35.197) 36.638,36.478 ccw(c37.918,35.197) 36.108,35.197 ; 36.108,35.197 ccw(c34.297,35.197) 35.578,36.478 cw(c34.297,35.197) 36.108,35.197 ; 40.868,29.536 cw(c39.587,28.256) 41.398,28.256 ccw(c39.587,28.256) 40.868,29.536 ; 40.868,29.536 ccw(c42.148,30.817) 42.148,29.006 cw(c42.148,30.817) 40.868,29.536 ; 42.148,26.445 cw(c43.959,26.445) 42.678,27.726 ccw(c43.959,26.445) 42.148,26.445 ; 42.148,26.445 ccw(c40.337,26.445) 41.618,27.726 cw(c40.337,26.445) 42.148,26.445 ; 42.148,26.761 cw(c40.337,26.761) 41.618,25.48 ccw(c40.337,26.761) 42.148,26.761 ; 42.148,26.761 ccw(c43.959,26.761) 42.678,25.48 cw(c43.959,26.761) 42.148,26.761
NetDis1_12: "Res Pack1.7" Dis1.12 U3.34 | length 37.6
  Bottom Layer w0.5: Dis1.12 38.648,34.296 44.688,28.256 U3.34 ; 38.648,35.197 cw(c40.458,35.197) 39.178,36.478 ccw(c40.458,35.197) 38.648,35.197 ; 38.648,35.197 ccw(c36.837,35.197) 38.118,36.478 cw(c36.837,35.197) 38.648,35.197 ; 43.408,29.536 cw(c42.127,28.256) 43.938,28.256 ccw(c42.127,28.256) 43.408,29.536 ; 43.408,29.536 ccw(c44.688,30.817) 44.688,29.006 cw(c44.688,30.817) 43.408,29.536 ; 44.688,26.445 cw(c46.499,26.445) 45.218,27.726 ccw(c46.499,26.445) 44.688,26.445 ; 44.688,26.445 ccw(c42.877,26.445) 44.158,27.726 cw(c42.877,26.445) 44.688,26.445 ; 44.688,26.761 cw(c42.877,26.761) 44.158,25.48 ccw(c42.877,26.761) 44.688,26.761 ; 44.688,26.761 ccw(c46.499,26.761) 45.218,25.48 cw(c46.499,26.761) 44.688,26.761
NetDis1_13: "Res Pack1.8" Dis1.13 U3.33 | length 37.6
  Bottom Layer w0.5: Dis1.13 41.188,34.296 47.228,28.256 U3.33 ; 41.188,35.197 cw(c42.998,35.197) 41.718,36.478 ccw(c42.998,35.197) 41.188,35.197 ; 41.188,35.197 ccw(c39.377,35.197) 40.658,36.478 cw(c39.377,35.197) 41.188,35.197 ; 45.948,29.536 cw(c44.667,28.256) 46.478,28.256 ccw(c44.667,28.256) 45.948,29.536 ; 45.948,29.536 ccw(c47.228,30.817) 47.228,29.006 cw(c47.228,30.817) 45.948,29.536 ; 47.228,26.445 cw(c49.039,26.445) 47.758,27.726 ccw(c49.039,26.445) 47.228,26.445 ; 47.228,26.445 ccw(c45.417,26.445) 46.698,27.726 cw(c45.417,26.445) 47.228,26.445 ; 47.228,26.761 cw(c45.417,26.761) 46.698,25.48 ccw(c45.417,26.761) 47.228,26.761 ; 47.228,26.761 ccw(c49.039,26.761) 47.758,25.48 cw(c49.039,26.761) 47.228,26.761
NetDis1_14: "Res Pack1.9" Dis1.14 U3.32 | length 37.6
  Bottom Layer w0.5: Dis1.14 43.728,34.296 49.768,28.256 U3.32 ; 43.728,35.197 cw(c45.539,35.197) 44.258,36.478 ccw(c45.539,35.197) 43.728,35.197 ; 43.728,35.197 ccw(c41.917,35.197) 43.198,36.478 cw(c41.917,35.197) 43.728,35.197 ; 48.488,29.536 cw(c47.207,28.256) 49.018,28.256 ccw(c47.207,28.256) 48.488,29.536 ; 48.488,29.536 ccw(c49.768,30.817) 49.768,29.006 cw(c49.768,30.817) 48.488,29.536 ; 49.768,26.445 cw(c51.579,26.445) 50.298,27.726 ccw(c51.579,26.445) 49.768,26.445 ; 49.768,26.445 ccw(c47.957,26.445) 49.238,27.726 cw(c47.957,26.445) 49.768,26.445 ; 49.768,26.761 cw(c47.957,26.761) 49.238,25.48 ccw(c47.957,26.761) 49.768,26.761 ; 49.768,26.761 ccw(c51.579,26.761) 50.298,25.48 cw(c51.579,26.761) 49.768,26.761
NetDis1_16: 9014.1 Dis1.16 | length 16.4
  Bottom Layer w0.5: Dis1.16 51.718,34.098 9014.1 ; 50.088,35.728 cw(c51.369,37.008) 49.558,37.008 ccw(c51.369,37.008) 50.088,35.728 ; 50.088,35.728 ccw(c48.808,34.447) 48.808,36.258 cw(c48.808,34.447) 50.088,35.728 ; 55.268,34.098 cw(c55.268,33.495) 55.695,33.921 ccw(c55.268,33.495) 55.268,34.098 ; 55.268,34.098 ccw(c55.268,34.702) 55.695,34.275 cw(c55.268,34.702) 55.268,34.098
NetP1_2: P1.2 U3.11 | length 20.6
  Bottom Layer w0.5: U3.11 54.848,8.952 57.408,6.392 58.424,6.392 P1.2 ; 58.648,6.168 cw(c57.367,4.888) 59.178,4.888 ccw(c57.367,4.888) 58.648,6.168 ; 58.648,6.168 ccw(c59.928,7.449) 59.928,5.638 cw(c59.928,7.449) 58.648,6.168 ; U3.11@54.848,8.46 cw(c54.848,7.272) 55.688,8.112 ccw(c54.848,7.272) U3.11@54.848,8.46 ; U3.11@55.098,9.21 ccw(c56.324,9.21) 55.457,8.343 cw(c56.324,9.21) U3.11@55.098,9.21 ; U3.11@55.598,9.21 ccw(c58.031,9.21) 56.311,7.489 cw(c58.031,9.21) U3.11@55.598,9.21
NetP1_3: P1.3 U3.10 | length 30.9
  Bottom Layer w0.5: U3.10 52.308,8.19 ; P1.3 55.61,4.888 ; U3.10@52.084,8.494 cw(c51.989,8.19) 52.308,8.19 ; U3.10@52.084,8.494 cw(c51.989,8.19) 52.308,8.19 ; U3.10@52.084,8.494 cw(c51.989,8.19) 52.308,8.19 ; U3.10@52.084,8.494 cw(c51.989,8.19) 52.308,8.19 ; 52.308,8.19 cw(c52.626,8.19) U3.10@52.531,8.494 ; 52.308,8.19 cw(c52.626,8.19) U3.10@52.531,8.494 ; 52.308,8.19 cw(c52.626,8.19) U3.10@52.531,8.494 ; 52.308,8.19 cw(c52.626,8.19) U3.10@52.531,8.494 ; 52.308,8.19 55.61,4.888 ; 55.61,4.888 cw(c55.61,3.156) 56.851,4.365 ccw(c55.61,3.156) 55.61,4.888 ; 55.61,4.888 ccw(c55.61,6.62) 56.851,5.412 cw(c55.61,6.62) 55.61,4.888 ; U3.10@52.058,9.21 ccw(c53.917,9.21) 52.602,7.896 cw(c53.917,9.21) U3.10@52.058,9.21 ; U3.10@52.558,9.21 ccw(c55.624,9.21) 53.456,7.042 cw(c55.624,9.21) U3.10@52.558,9.21 ; U3.10@53.058,9.21 ccw(c57.331,9.21) 54.309,6.189 cw(c57.331,9.21) U3.10@53.058,9.21
NetQ1_2: 9014.2 R6.2 | length 11.4
  Bottom Layer w0.5: 9014.2 R6.2@60.182,32.828 ; 57.475,32.828 cw(c57.475,33.432) 57.049,33.005 ccw(c57.475,33.432) 57.475,32.828 ; 57.475,32.828 ccw(c57.475,32.225) 57.049,32.651 cw(c57.475,32.225) 57.475,32.828 ; 58.879,32.828 cw(c58.879,31.017) 60.16,32.298 ccw(c58.879,31.017) 58.879,32.828 ; 58.879,32.828 ccw(c58.879,34.639) 60.16,33.358 cw(c58.879,34.639) 58.879,32.828
NetR2_1: R2.1 U2.5 U3.4 | length 48.2
  Bottom Layer w0.5: R2.1 U2.5 35.925,20.128 37.068,18.985 U3.4 ; U2.5@24.368,21.111 cw(c26.179,21.111) 24.898,22.392 ccw(c26.179,21.111) U2.5@24.368,21.111 ; U2.5@24.368,21.111 ccw(c22.557,21.111) 23.838,22.392 cw(c22.557,21.111) U2.5@24.368,21.111 ; R2.1@24.368,21.939 cw(c22.557,21.939) 23.838,20.658 ccw(c22.557,21.939) R2.1@24.368,21.939 ; R2.1@24.368,21.939 ccw(c26.179,21.939) U2.5@24.898,20.658 ; R2.1@24.368,21.939 ccw(c26.179,21.939) U2.5@24.898,20.658 ; U2.5@24.898,20.658 ccw(c26.179,21.939) 26.179,20.128 ; U2.5@24.898,20.658 ccw(c26.179,21.939) 26.179,20.128 ; 26.179,20.128 ccw(c26.179,18.317) 24.898,19.598 cw(c26.179,18.317) 26.179,20.128 ; 37.068,11.521 cw(c35.257,11.521) 36.538,10.24 ccw(c35.257,11.521) 37.068,11.521 ; 37.068,11.521 ccw(c38.879,11.521) 37.598,10.24 cw(c38.879,11.521) 37.068,11.521
NetR3_1: R3.1 U2.6 U3.3 | length 48.9
  Bottom Layer w0.5: R3.1 U2.6 21.828,19.493 23.225,18.096 32.75,18.096 34.528,16.318 U3.3 ; 21.828,21.939 cw(c20.017,21.939) 21.298,20.658 ccw(c20.017,21.939) 21.828,21.939 ; 21.828,21.939 ccw(c23.639,21.939) 22.358,20.658 cw(c23.639,21.939) 21.828,21.939 ; 21.828,23.143 cw(c23.639,23.143) 22.358,24.424 ccw(c23.639,23.143) 21.828,23.143 ; 21.828,23.143 ccw(c20.017,23.143) 21.298,24.424 cw(c20.017,23.143) 21.828,23.143 ; 34.528,11.521 cw(c32.717,11.521) 33.998,10.24 ccw(c32.717,11.521) 34.528,11.521 ; 34.528,11.521 ccw(c36.339,11.521) 35.058,10.24 cw(c36.339,11.521) 34.528,11.521 ; U2.6@22.066,20.053 ccw(c23.066,19.737) 22.325,18.996 cw(c23.066,19.737) U2.6@22.066,20.053 ; U2.6@22.543,19.902 ccw(c23.952,19.458) 22.907,18.414 cw(c23.952,19.458) U2.6@22.543,19.902
NetR4_1: R4.1 U2.7 U3.2 | length 51.3
  Bottom Layer w0.5: R4.1 U2.7 19.288,17.842 20.939,16.191 30.718,16.191 31.988,14.921 U3.2 ; 19.288,18.317 cw(c21.099,18.317) 19.818,19.598 ccw(c21.099,18.317) 19.288,18.317 ; 19.288,18.317 ccw(c17.477,18.317) 18.758,19.598 cw(c17.477,18.317) 19.288,18.317 ; 19.288,21.939 cw(c17.477,21.939) 18.758,20.658 ccw(c17.477,21.939) 19.288,21.939 ; 19.288,21.939 ccw(c21.099,21.939) 19.818,20.658 cw(c21.099,21.939) 19.288,21.939 ; 19.288,25.175 cw(c21.099,25.175) 19.818,26.456 ccw(c21.099,25.175) 19.288,25.175 ; 19.288,25.175 ccw(c17.477,25.175) 18.758,26.456 cw(c17.477,25.175) 19.288,25.175 ; 31.988,11.521 cw(c30.177,11.521) 31.458,10.24 ccw(c30.177,11.521) 31.988,11.521 ; 31.988,11.521 ccw(c33.799,11.521) 32.518,10.24 cw(c33.799,11.521) 31.988,11.521
NetR7_2: R7.2 U3.1 U4.2 | length 40.8
  Bottom Layer w0.5: U4.2 11.16,12.508 R7.2 ; U4.2@4.401,12.155 cw(c5.255,11.301) 5.255,12.508 cw(c5.255,13.715) U4.2@4.401,12.862 ; 9.894,12.508 ccw(c9.894,14.028) R7.2@10.969,12.953 ; 10.507,12.508 cw(c10.507,11.855) R7.2@10.969,12.317 ; R7.2@11.287,12.381 13.7,14.54 28.051,14.54 29.448,13.143 U3.1@29.448,9.841 ; R7.2@11.312,13.084 ccw(c11.408,14.814) 12.563,13.523 ; 29.448,11.521 cw(c27.637,11.521) 28.918,10.24 ccw(c27.637,11.521) 29.448,11.521 ; 29.448,11.521 ccw(c31.259,11.521) 29.978,10.24 cw(c31.259,11.521) 29.448,11.521
NetS1_1: S1.1 U3.24 | length 39.2
  Top Layer w0.5: S1.1 61.452,36.384 67.268,36.384 70.088,33.565 v1(70.088,30.288) ; 61.08,36.756 cw(c62.232,37.908) 60.603,37.908 ccw(c62.232,37.908) 61.08,36.756 ; 61.08,36.756 ccw(c59.928,35.604) 59.928,37.233 cw(c59.928,35.604) 61.08,36.756 ; 70.088,31.495 cw(c68.881,31.495) 69.734,30.642 ccw(c68.881,31.495) 70.088,31.495 ; 70.088,31.495 ccw(c71.295,31.495) 70.441,30.642 cw(c71.295,31.495) 70.088,31.495
  Bottom Layer w0.5: U3.24 v1(70.088,30.288) ; 70.088,26.761 cw(c68.277,26.761) 69.558,25.48 ccw(c68.277,26.761) 70.088,26.761 ; 70.088,26.761 ccw(c71.899,26.761) 70.618,25.48 cw(c71.899,26.761) 70.088,26.761 ; 70.088,29.081 cw(c71.295,29.081) 70.441,29.935 ccw(c71.295,29.081) 70.088,29.081 ; 70.088,29.081 ccw(c68.881,29.081) 69.734,29.935 cw(c68.881,29.081) 70.088,29.081
NetS2_1: S2.1 U3.23 | length 32.7
  Top Layer w0.5: S2.1 72.628,35.368 v1(72.628,30.288) ; 71.24,36.756 cw(c72.392,37.908) 70.763,37.908 ccw(c72.392,37.908) 71.24,36.756 ; 71.24,36.756 ccw(c70.088,35.604) 70.088,37.233 cw(c70.088,35.604) 71.24,36.756 ; 72.628,31.495 cw(c71.421,31.495) 72.274,30.642 ccw(c71.421,31.495) 72.628,31.495 ; 72.628,31.495 ccw(c73.835,31.495) 72.981,30.642 cw(c73.835,31.495) 72.628,31.495
  Bottom Layer w0.5: U3.23 v1(72.628,30.288) ; 72.628,26.761 cw(c70.817,26.761) 72.098,25.48 ccw(c70.817,26.761) 72.628,26.761 ; 72.628,26.761 ccw(c74.439,26.761) 73.158,25.48 cw(c74.439,26.761) 72.628,26.761 ; 72.628,29.081 cw(c73.835,29.081) 72.981,29.935 ccw(c73.835,29.081) 72.628,29.081 ; 72.628,29.081 ccw(c71.421,29.081) 72.274,29.935 cw(c71.421,29.081) 72.628,29.081
NetS3_1: S3.1 U3.22 | length 33.7
  Top Layer w0.5: v1(75.168,30.288) 75.168,32.828 S3.1 ; 75.168,31.495 cw(c73.961,31.495) 74.814,30.642 ccw(c73.961,31.495) 75.168,31.495 ; 75.168,31.495 ccw(c76.375,31.495) 75.521,30.642 cw(c76.375,31.495) 75.168,31.495 ; 79.096,36.756 cw(c80.248,35.604) 80.248,37.233 ccw(c80.248,35.604) 79.096,36.756 ; 79.096,36.756 ccw(c77.943,37.908) 79.573,37.908 cw(c77.943,37.908) 79.096,36.756
  Bottom Layer w0.5: U3.22 v1(75.168,30.288) ; 75.168,26.761 cw(c73.357,26.761) 74.638,25.48 ccw(c73.357,26.761) 75.168,26.761 ; 75.168,26.761 ccw(c76.979,26.761) 75.698,25.48 cw(c76.979,26.761) 75.168,26.761 ; 75.168,29.081 cw(c76.375,29.081) 75.521,29.935 ccw(c76.375,29.081) 75.168,29.081 ; 75.168,29.081 ccw(c73.961,29.081) 74.814,29.935 cw(c73.961,29.081) 75.168,29.081
VCC: 9014.3 "Res Pack1.1" C2.2 C3.1 Dis1.2 R1.3 R2.2 R3.2 R4.2 R7.1 U1.2 U2.8 U3.31 U3.40 U4.3 | length 372.8
  Top Layer w0.5: R4.2@11.414,27.24 R4.2@11.668,27.621 ; R4.2 13.248,28.566 v1(13.248,32.391) v1@13.446,32.193 ; v1@26.554,21.807 cw(c25.701,20.953) 26.908,20.953 cw(c28.115,20.953) v1@27.261,21.807 ; v1@26.636,21.888 cw(c25.978,21.231) 26.908,21.231 cw(c27.837,21.231) v1@27.18,21.888 ; v1(26.908,22.16) 26.908,7.428 v1(29.448,4.888) ; v1@28.948,4.888 ccw(c27.741,4.888) 28.594,5.742 ccw(c29.448,6.595) v1@29.448,5.388 ; v1@29.063,4.888 ccw(c28.133,4.888) 28.791,5.545 ccw(c29.448,6.203) v1@29.448,5.273 ; U3.31 52.308,26.351 ; 9014.3 56.372,30.415 52.308,26.351 ; 12.948,28.266 cw(c11.668,29.547) 11.668,27.736 ccw(c11.668,29.547) 12.948,28.266 ; 12.948,28.266 ccw(c14.229,26.986) 12.418,26.986 cw(c14.229,26.986) 12.948,28.266 ; 13.248,31.184 cw(c14.455,31.184) 13.601,32.038 ccw(c14.455,31.184) 13.248,31.184 ; 13.248,31.184 ccw(c12.041,31.184) 12.894,32.038 cw(c12.041,31.184) 13.248,31.184 ; 52.308,26.351 cw(c51.374,26.351) 51.892,25.574 ccw(c51.374,26.351) 52.308,26.351 ; 52.308,26.351 ccw(c53.241,26.351) 52.724,25.574 cw(c53.241,26.351) 52.308,26.351 ; 56.372,30.954 cw(c56.976,30.954) 56.549,31.381 ccw(c56.975,30.955) 56.372,30.955 ; 56.372,30.955 ccw(c55.768,30.955) 56.195,31.381 cw(c55.768,30.955) 56.372,30.955
  Bottom Layer w0.5: U4.3 9.255,20.255 R7.1 ; 8.112,19.112 R1.3 8.874,26.986 ; R7.1@10.969,19.937 ccw(c10.2,19.169) 10.2,20.255 ccw(c10.2,21.342) R7.1@10.969,20.573 ; R4.2 13.7,24.954 R3.2 16.24,22.922 R2.2 U2.8 ; v1(13.248,32.391) Dis1.2 ; v1(26.908,22.16) U3.40 25.384,28.764 16.24,28.764 14.462,26.986 8.874,26.986 ; v1@26.908,22.545 ccw(c26.908,23.475) 27.565,22.817 ccw(c28.222,22.16) v1@27.293,22.16 ; v1@26.908,22.66 ccw(c26.908,23.867) 27.761,23.014 ccw(c28.615,22.16) v1@27.408,22.16 ; v1(29.448,4.888) C3.1 39.521,1.808 87.995,1.808 C2.2 92.948,4.888 95.488,7.428 U1.2 ; 29.448,28.256 29.448,23.278 ; v1@29.72,4.616 cw(c30.377,3.959) 30.377,4.888 cw(c30.377,5.818) v1@29.72,5.16 ; v1@29.801,4.535 cw(c30.655,3.681) 30.655,4.888 cw(c30.655,6.095) v1@29.801,5.242 ; C3.1@36.578,4.358 ccw(c35.297,3.077) 35.297,4.888 ccw(c35.297,6.699) C3.1@36.578,5.418 ; C3.1@36.843,4.623 ccw(c36.203,3.983) 36.203,4.888 ccw(c36.203,5.793) C3.1@36.843,5.153 ; 37.017,4.144 cw(c36.799,2.346) 38.225,3.463 cw(c39.65,4.579) 37.852,4.798 ; C3.1@37.063,4.516 cw(c36.954,3.617) 37.666,4.175 cw(c38.379,4.734) C3.1@37.48,4.843 ; U3.31 52.308,23.278 ; 4.901,15.902 cw(c4.048,16.755) 4.048,15.548 ccw(c4.048,16.755) 4.901,15.902 ; 4.901,15.902 ccw(c5.755,15.048) 4.548,15.048 cw(c5.755,15.048) 4.901,15.902 ; 8.112,25.937 cw(c9.923,25.937) 8.642,27.218 ccw(c9.923,25.937) 8.112,25.937 ; 8.112,25.937 ccw(c6.301,25.937) 7.582,27.218 cw(c6.301,25.937) 8.112,25.937 ; 8.874,26.986 cw(c9.156,27.268) 8.793,27.435 ccw(c9.156,27.268) 8.874,26.986 ; 8.874,26.986 ccw(c8.592,26.704) 8.425,27.067 cw(c8.592,26.704) 8.874,26.986 ; 9.857,26.986 cw(c9.857,25.175) 11.138,26.456 ccw(c9.857,25.175) 9.857,26.986 ; 9.857,26.986 ccw(c9.857,28.797) 11.138,27.516 cw(c9.857,28.797) 9.857,26.986 ; 12.948,25.706 cw(c14.229,26.986) 12.418,26.986 ccw(c14.229,26.986) 12.948,25.706 ; 12.948,25.706 ccw(c11.668,24.425) 11.668,26.236 cw(c11.668,24.425) 12.948,25.706 ; 13.248,33.598 cw(c12.041,33.598) 12.894,32.745 ccw(c12.041,33.598) 13.248,33.598 ; 13.248,33.598 ccw(c14.455,33.598) 13.601,32.745 cw(c14.455,33.598) 13.248,33.598 ; 13.248,35.197 cw(c15.059,35.197) 13.778,36.478 ccw(c15.059,35.197) 13.248,35.197 ; 13.248,35.197 ccw(c11.437,35.197) 12.718,36.478 cw(c11.437,35.197) 13.248,35.197 ; 13.479,26.986 cw(c13.479,28.797) 12.198,27.516 ccw(c13.479,28.797) 13.479,26.986 ; 13.479,26.986 ccw(c13.479,25.175) 12.198,26.456 cw(c13.479,25.175) 13.479,26.986 ; 15.488,23.674 cw(c16.769,24.954) 14.958,24.954 ccw(c16.769,24.954) 15.488,23.674 ; 15.488,23.674 ccw(c14.208,22.393) 14.208,24.204 cw(c14.208,22.393) 15.488,23.674 ; U2.8@16.748,21.111 cw(c18.559,21.111) 17.278,22.392 ccw(c18.559,21.111) U2.8@16.748,21.111 ; U2.8@16.748,21.111 ccw(c14.937,21.111) 16.218,22.392 cw(c14.937,21.111) U2.8@16.748,21.111 ; R2.2@16.748,21.939 cw(c14.937,21.939) 16.218,20.658 ccw(c14.937,21.939) R2.2@16.748,21.939 ; R2.2@16.748,21.939 ccw(c18.559,21.939) 17.278,20.658 cw(c18.559,21.939) R2.2@16.748,21.939 ; U3.40@29.133,23.769 cw(c28.907,23.278) 29.448,23.278 ; U3.40@29.133,23.769 cw(c28.907,23.278) 29.448,23.278 ; U3.40@29.133,23.769 cw(c28.907,23.278) 29.448,23.278 ; U3.40@29.133,23.769 cw(c28.907,23.278) 29.448,23.278 ; 29.448,23.278 cw(c29.989,23.278) U3.40@29.762,23.769 ; 29.448,23.278 cw(c29.989,23.278) U3.40@29.762,23.769 ; 29.448,23.278 cw(c29.989,23.278) U3.40@29.762,23.769 ; 29.448,23.278 cw(c29.989,23.278) U3.40@29.762,23.769 ; 29.448,23.278 29.956,22.77 51.8,22.77 52.308,23.278 ; 29.448,26.445 cw(c31.259,26.445) 29.978,27.726 ccw(c31.259,26.445) 29.448,26.445 ; 29.448,26.445 ccw(c27.637,26.445) 28.918,27.726 cw(c27.637,26.445) 29.448,26.445 ; 29.448,26.761 cw(c27.637,26.761) 28.918,25.48 ccw(c27.637,26.761) 29.448,26.761 ; 29.448,26.761 ccw(c31.259,26.761) 29.978,25.48 cw(c31.259,26.761) 29.448,26.761 ; 52.308,23.278 cw(c52.849,23.278) 52.622,23.769 ccw(c52.849,23.278) 52.308,23.278 ; 52.308,23.278 ccw(c51.767,23.278) 51.993,23.769 cw(c51.767,23.278) 52.308,23.278 ; 89.291,3.463 cw(c90.717,2.346) 90.498,4.144 ccw(c90.717,2.346) 89.291,3.463 ; 89.291,3.463 ccw(c87.866,4.579) 89.663,4.798 cw(c87.866,4.579) 89.291,3.463 ; 92.219,4.888 cw(c92.219,6.699) 90.938,5.418 ccw(c92.219,6.699) 92.219,4.888 ; 92.219,4.888 ccw(c92.219,3.077) 90.938,4.358 cw(c92.219,3.077) 92.219,4.888 ; 95.488,8.157 cw(c97.299,8.157) 96.018,9.438 ccw(c97.299,8.157) 95.488,8.157 ; 95.488,8.157 ccw(c93.677,8.157) 94.958,9.438 cw(c93.677,8.157) 95.488,8.157 ; R1.3@7.935,27.571 ccw(c9.348,28.984) 9.348,26.986 cw(c9.348,28.984) R1.3@7.935,27.571 ; R1.3@8.289,27.925 ccw(c10.555,30.191) 10.555,26.986 cw(c10.555,30.191) R1.3@8.289,27.925 ; R1.3@8.642,28.278 ccw(c11.762,31.398) 11.762,26.986 cw(c11.762,31.398) R1.3@8.642,28.278 ; R4.2@12.06,26.594 ccw(c14.208,28.741) 14.208,25.704 cw(c14.208,28.741) R4.2@12.06,26.594 ; 12.914,25.74 ccw(c14.208,27.034) 14.208,25.204 cw(c14.208,27.034) 12.914,25.74 ; 13.287,25.367 cw(c12.874,24.954) 13.458,24.954 ccw(c12.874,24.954) 13.287,25.367 ; R3.2@14.6,24.562 ccw(c16.748,26.709) 16.748,23.672 cw(c16.748,26.709) R3.2@14.6,24.562 ; 15.454,23.708 ccw(c16.748,25.002) 16.748,23.172 cw(c16.748,25.002) 15.454,23.708 ; 15.827,23.335 cw(c15.414,22.922) 15.998,22.922 ccw(c15.414,22.922) 15.827,23.335 ; 27.741,22.993 cw(c29.448,21.286) 29.448,23.7 ccw(c29.448,21.286) 27.741,22.993 ; 27.741,26.407 ccw(c29.448,28.114) 29.448,25.7 cw(c29.448,28.114) 27.741,26.407 ; 28.344,23.597 ccw(c27.491,24.45) 28.698,24.45 cw(c27.491,24.45) 28.344,23.597 ; 28.344,25.804 cw(c27.491,24.95) 28.698,24.95 ccw(c27.491,24.95) 28.344,25.804 ; 28.594,23.847 cw(c29.448,22.993) 29.448,24.2 ccw(c29.448,22.993) 28.594,23.847 ; 28.594,25.554 ccw(c29.448,26.407) 29.448,25.2 cw(c29.448,26.407) 28.594,25.554
VEE: Dis1.3 R1.1 | length 28.9
  Bottom Layer w0.5: R1.1 9.128,32.828 11.668,30.288 14.97,30.288 15.788,31.106 Dis1.3 ; 7.383,32.828 cw(c7.383,34.639) 6.102,33.358 ccw(c7.383,34.639) 7.383,32.828 ; 7.383,32.828 ccw(c7.383,31.017) 6.102,32.298 cw(c7.383,31.017) 7.383,32.828 ; 15.788,35.197 cw(c17.599,35.197) 16.318,36.478 ccw(c17.599,35.197) 15.788,35.197 ; 15.788,35.197 ccw(c13.977,35.197) 15.258,36.478 cw(c13.977,35.197) 15.788,35.197
pads on no net: U3.5 U3.6 U3.7 U3.8 U3.12 U3.13 U3.14 U3.15 U3.16 U3.17 U3.21 U3.29 U3.30
copper on no net: | length 5.1
  Top Layer w0.127: 1.98,3.15 4.52,3.15 ; 3.25,1.88 3.25,4.42

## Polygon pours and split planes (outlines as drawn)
GND on Bottom Layer (solid, remove dead copper): -2.54,42.291 -2.54,-1.143 103.632,-1.143 103.632,42.418 -2.286,42.418
GND on Bottom Layer (solid, remove dead copper, shelved): -3.572,80.961 -3.572,42.48 96.123,42.48 96.123,80.961
GND on Bottom Layer (solid, remove dead copper, shelved): -4.334,81.596 -4.334,40.702 97.393,40.702 97.393,82.485 -4.588,82.485 -4.588,80.707
GND on Bottom Layer (solid, remove dead copper, shelved): -0.016,40.321 -0.016,0.062 101.457,0.062 101.457,40.448 -0.016,40.448
GND on Bottom Layer (hatched 90Degree grid 0.508 track 0.254, remove dead copper, shelved): 0,40.259 0,0.127 101.6,0.127 101.6,40.259

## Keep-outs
Keep-Out Layer:
  lines w0.254: -0.016,0.062 -0.016,40.321 101.457,40.321 101.584,40.194 101.584,0.189 101.457,0.062 -0.016,0.062

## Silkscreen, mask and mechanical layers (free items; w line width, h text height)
Top Overlay:
  text "Design" at 79.629,30.988 h1.52
  text "By May19th" at 75.438,27.94 h1.52
Mechanical 1:
  lines w0.127: 0,40.3 0,0 101.5,0 101.5,40.3
  lines w0.254: -1.946,1.526 -1.438,0.002 ; -1.946,38.778 -1.438,40.302 ; -1.692,0.002 -1.184,0.002 ; -1.692,40.302 -1.184,40.302 ; -1.438,13.651 -1.438,0.002 ; -1.438,26.652 -1.438,40.302 ; -0.93,1.526 -1.438,0.002 ; -0.93,38.778 -1.438,40.302 ; -0.07,41.972 -0.07,42.48 ; 0,40.3 101.5,40.3 ; 1.454,41.718 -0.07,42.226 ; 1.454,42.734 -0.07,42.226 ; 43.672,42.226 -0.07,42.226 ; 57.688,42.226 101.43,42.226 ; 99.906,41.718 101.43,42.226 ; 99.906,42.734 101.43,42.226 ; 101.43,41.972 101.43,42.48
  text "101.5 (mm)" at 43.926,41.312 h1.52
  text "40.3 (mm)" at -0.524,13.905 h1.52 r90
